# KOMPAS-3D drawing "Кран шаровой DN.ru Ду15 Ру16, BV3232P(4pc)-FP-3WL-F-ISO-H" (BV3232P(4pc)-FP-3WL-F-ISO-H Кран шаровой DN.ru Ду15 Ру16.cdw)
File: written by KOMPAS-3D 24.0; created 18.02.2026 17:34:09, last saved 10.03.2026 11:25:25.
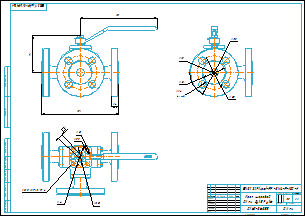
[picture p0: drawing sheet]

Document properties: Автор: R2D2; Форматы листов документа: A2; Полное имя файла: BV3232P(4pc)-FP-3WL-F-ISO-H Кран шаровой DN.ru Ду15 Ру16.m3d; Масса: 3.5; Наименование: Кран шаровой DN.ru Ду15 Ру16; Количество листов документа: 1; Примечание: D160-36355

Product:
- Part/product: Кран шаровой DN.ru Ду15 Ру16  | designation BV3232P(4pc)-FP-3WL-F-ISO-H
    Масса: 3.5
    Раздел спецификации: Прочие изделия
    Форматы листов документа: A2
    Примечание: D160-36355

Views: Вид 1, Спереди, Проекционный вид 2
Referenced files in E:\Работа\Зайцев\BV3232P(4pc)-FP-3WL-F-ISO-H Кран шаровой DN.ru Ду15-100 Ру16\DN15\: BV3232P(4pc)-FP-3WL-F-ISO-H Кран шаровой DN.ru Ду15 Ру16.m3d
Referenced files in E:\Работа\Зайцев\Для компаса\: чертеж DN.ru А3.cdt
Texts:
  BV3232P(4pc)-FP-3WL-F-ISO-H
  чертеж DN.ru А3.cdt
  Кран шаровой
  DN.ru Ду15 Ру16
  Кран шаровой DN.ru Ду15 Ру16
  BV3232P(4pc)-FP-3WL-F-ISO-H Кран шаровой DN.ru Ду15 Ру16
Dimensions and other numbers on the sheet: 0; 3; 2; 4; 150; 14; 72; 95; 65; 45; 15; 4 отв.; 1:1; 1; 3,5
